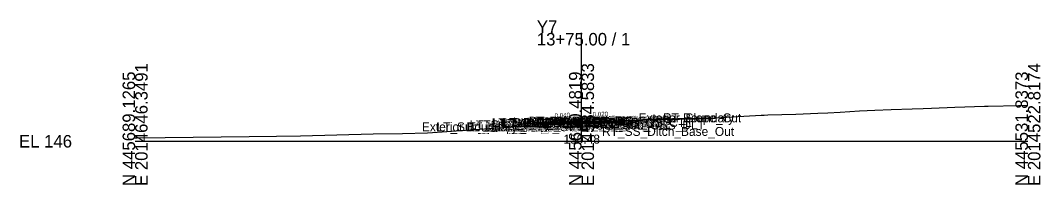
# Model space of a CAD drawing. Extents: x -26 to 203, y -10 to 7527.
# Drawn here: x -25.7 to 202.8, y 7490.3 to 7527 of the extents above; entities that cross this region are included whole.
import ezdxf

# ---------------------------------------------------------------- set-up
doc = ezdxf.new("R2010")
doc.units = 0
for name, color, linetype in [('Exist CMT Pavement', 7, 'Continuous'), ('Exist Cross Section Cell', 7, 'Continuous'), ('Exist XS Center Line Elevation Label', 7, 'Continuous'), ('Exist XS Ground Line', 7, 'Continuous'), ('Prop CMT Pvmt Course 1', 7, 'Continuous'), ('Prop CMT Pvmt Course 1 Wedge', 7, 'Continuous'), ('Prop CMT Pvmt Course 2', 7, 'Continuous'), ('Prop CMT Pvmt Course 2 Wedge', 7, 'Continuous'), ('Prop CMT Pvmt Course 3', 7, 'Continuous'), ('Prop CMT Pvmt Course 3 Wedge', 7, 'Continuous'), ('Prop CMT Pvmt Surface', 7, 'Continuous'), ('Prop CMT Pvmt Surface Shoulder', 7, 'Continuous'), ('Prop CMT Pvmt Wedge Surface 1', 7, 'Continuous'), ('Prop CMT Pvmt Wedge Surface 2', 7, 'Continuous'), ('Prop CMT Pvmt Wedge Surface 3', 7, 'Continuous'), ('Prop CMT Shld Paved Course 1', 7, 'Continuous'), ('Prop CMT Shld Paved Course 2', 7, 'Continuous'), ('Prop CMT Shld Paved Course 3', 7, 'Continuous'), ('Prop CMT Slope Grass', 7, 'Continuous'), ('Prop CMT Subgrade Earthwork', 7, 'Continuous'), ('Prop XS Earthwork Shape', 7, 'Continuous'), ('Prop XS SE Text', 7, 'Continuous'), ('Prop XS Side Slope Text', 7, 'Continuous'), ('Scratch_Level_0', 7, 'Continuous')]:
    doc.layers.add(name, color=color, linetype=linetype)

msp = doc.modelspace()

# ---------------------------------------------------------------- linework, layer by layer
at = {"layer": 'Exist CMT Pavement'}
msp.add_lwpolyline([(92.55, 7504.17), (98.8, 7504.43), (99.58, 7504.47), (100, 7504.48), (101.24, 7504.49), (107.57, 7504.59)], dxfattribs=at)
at = {"layer": 'Exist Cross Section Cell'}
for p, q in [((100, 7500), (100, 7524.24)), ((0, 7500), (100, 7500)), ((100, 7500), (200, 7500))]:
    msp.add_line(p, q, dxfattribs=at)
at = {"layer": 'Exist XS Ground Line'}
msp.add_lwpolyline([(0, 7500.78), (0.48, 7500.79), (25.52, 7501.08), (31.67, 7501.15), (37.07, 7501.23), (53.32, 7501.64), (59.89, 7501.77), (65.51, 7501.87), (68.77, 7502.08), (84.52, 7503.23), (85.44, 7503.31), (90.98, 7503.89), (91.38, 7504.13), (91.72, 7504.13), (98.8, 7504.43), (99.58, 7504.47), (100, 7504.48), (101.24, 7504.49), (108.29, 7504.6), (108.58, 7504.86), (109, 7504.59), (113.67, 7504.72), (116.69, 7504.88), (117.85, 7504.9), (126.1, 7505.05), (127.54, 7505.12), (133.78, 7505.47), (140.26, 7505.83), (140.9, 7505.86), (141.72, 7505.89), (148.02, 7506.06), (152.97, 7506.29), (155.15, 7506.38), (157.91, 7506.52), (162.27, 7506.8), (165.69, 7506.95), (169.39, 7507.12), (174.1, 7507.24), (176.51, 7507.37), (178.41, 7507.41), (183.64, 7507.62), (190.29, 7507.87), (190.76, 7507.89), (191.13, 7507.89), (197.88, 7508.03), (200, 7508.08)], dxfattribs=at)
at = {"layer": 'Prop CMT Pvmt Course 1'}
for points in [[(100, 7504.5), (91.55, 7504.17)], [(91.55, 7504.17), (91.55, 7503.92)], [(91.55, 7503.92), (92.55, 7503.96)], [(92.55, 7504.08), (100, 7504.38)], [(92.55, 7503.96), (92.55, 7504.08)], [(100, 7504.5), (108.57, 7504.68)], [(107.57, 7504.53), (100, 7504.38)], [(100, 7504.25), (100, 7504.5)], [(100, 7504.25), (100, 7504.5)], [(100, 7504.38), (100, 7504.25), (100, 7504.25)], [(100, 7504.38), (100, 7504.25), (100, 7504.25)], [(107.57, 7504.41), (107.57, 7504.53)], [(108.57, 7504.43), (107.57, 7504.41)], [(108.57, 7504.68), (108.57, 7504.43)]]:
    msp.add_lwpolyline(points, dxfattribs=at)
at = {"layer": 'Prop CMT Pvmt Course 1 Wedge'}
for points in [[(100, 7504.38), (92.55, 7504.08)], [(100, 7504.38), (107.57, 7504.53)]]:
    msp.add_lwpolyline(points, dxfattribs=at)
at = {"layer": 'Prop CMT Pvmt Course 2'}
for points in [[(92.55, 7503.96), (91.55, 7503.92)], [(91.55, 7503.92), (91.55, 7503.67)], [(91.55, 7503.67), (92.55, 7503.71)], [(92.55, 7503.71), (92.55, 7503.96)], [(107.57, 7504.41), (108.57, 7504.43)], [(107.57, 7504.16), (107.57, 7504.41)], [(108.57, 7504.18), (107.57, 7504.16)], [(108.57, 7504.43), (108.57, 7504.18)]]:
    msp.add_lwpolyline(points, dxfattribs=at)
at = {"layer": 'Prop CMT Pvmt Course 2 Wedge'}
for points in [[(100, 7504.25), (92.55, 7503.96)], [(100, 7504.25), (107.57, 7504.41)]]:
    msp.add_lwpolyline(points, dxfattribs=at)
at = {"layer": 'Prop CMT Pvmt Course 3'}
for points in [[(92.55, 7503.71), (91.55, 7503.67)], [(91.55, 7503.67), (91.55, 7503.29)], [(91.55, 7503.29), (92.55, 7503.33)], [(92.55, 7503.33), (92.55, 7503.71)], [(107.57, 7504.16), (108.57, 7504.18)], [(107.57, 7503.78), (107.57, 7504.16)], [(108.57, 7503.8), (107.57, 7503.78)], [(108.57, 7504.18), (108.57, 7503.8)]]:
    msp.add_lwpolyline(points, dxfattribs=at)
at = {"layer": 'Prop CMT Pvmt Course 3 Wedge'}
for points in [[(100, 7504), (92.55, 7503.71)], [(100, 7504), (107.57, 7504.16)]]:
    msp.add_lwpolyline(points, dxfattribs=at)
at = {"layer": 'Prop CMT Pvmt Surface'}
for points in [[(100, 7504.5), (91.55, 7504.17)], [(100, 7504.5), (108.57, 7504.68)]]:
    msp.add_lwpolyline(points, dxfattribs=at)
at = {"layer": 'Prop CMT Pvmt Surface Shoulder'}
for points in [[(91.55, 7504.17), (91.55, 7504.17)], [(108.57, 7504.68), (108.57, 7504.68)]]:
    msp.add_lwpolyline(points, dxfattribs=at)
at = {"layer": 'Prop CMT Pvmt Wedge Surface 1'}
for points in [[(91.55, 7503.92), (91.55, 7504.17)], [(92.55, 7503.96), (91.55, 7503.92)], [(100, 7504.38), (92.55, 7504.08)], [(92.55, 7504.08), (92.55, 7503.96)], [(100, 7504.38), (107.57, 7504.53)], [(107.57, 7504.53), (107.57, 7504.41)], [(107.57, 7504.41), (108.57, 7504.43)], [(108.57, 7504.43), (108.57, 7504.68)]]:
    msp.add_lwpolyline(points, dxfattribs=at)
at = {"layer": 'Prop CMT Pvmt Wedge Surface 2'}
for points in [[(100, 7504.25), (91.55, 7503.92)], [(91.55, 7503.92), (91.55, 7504.17)], [(100, 7504.25), (108.57, 7504.43)], [(108.57, 7504.43), (108.57, 7504.68)]]:
    msp.add_lwpolyline(points, dxfattribs=at)
at = {"layer": 'Prop CMT Pvmt Wedge Surface 3'}
for points in [[(91.55, 7503.67), (91.55, 7504.17)], [(100, 7504), (91.55, 7503.67)], [(100, 7504), (108.57, 7504.18)], [(108.57, 7504.18), (108.57, 7504.68)]]:
    msp.add_lwpolyline(points, dxfattribs=at)
at = {"layer": 'Prop CMT Shld Paved Course 1'}
for points in [[(91.55, 7504.17), (91.3, 7503.91)], [(91.3, 7503.91), (91.55, 7503.92)], [(91.55, 7504.17), (91.55, 7504.17)], [(91.55, 7503.92), (91.55, 7504.17)], [(108.57, 7504.68), (108.57, 7504.68)], [(108.57, 7504.68), (108.82, 7504.42)], [(108.57, 7504.43), (108.57, 7504.68)], [(108.82, 7504.42), (108.57, 7504.43)]]:
    msp.add_lwpolyline(points, dxfattribs=at)
at = {"layer": 'Prop CMT Shld Paved Course 2'}
for points in [[(91.55, 7503.92), (91.3, 7503.91), (91.04, 7503.66)], [(91.04, 7503.66), (91.55, 7503.67)], [(91.55, 7503.67), (91.55, 7503.92)], [(108.57, 7504.43), (108.82, 7504.42), (109.08, 7504.17)], [(108.57, 7504.18), (108.57, 7504.43)], [(109.08, 7504.17), (108.57, 7504.18)]]:
    msp.add_lwpolyline(points, dxfattribs=at)
at = {"layer": 'Prop CMT Shld Paved Course 3'}
for points in [[(90.16, 7503.26), (91.55, 7503.29)], [(91.55, 7503.67), (91.04, 7503.66), (90.66, 7503.27)], [(91.55, 7503.29), (91.55, 7503.67)], [(108.57, 7503.8), (108.57, 7504.18)], [(108.57, 7504.18), (109.08, 7504.17), (109.46, 7503.78)], [(109.96, 7503.77), (108.57, 7503.8)]]:
    msp.add_lwpolyline(points, dxfattribs=at)
at = {"layer": 'Prop CMT Slope Grass'}
for points in [[(108.57, 7504.68), (128.53, 7505.18)], [(91.55, 7504.17), (85.55, 7503.69), (84.08, 7503.2)]]:
    msp.add_lwpolyline(points, dxfattribs=at)
at = {"layer": 'Prop CMT Subgrade Earthwork'}
msp.add_line((109.96, 7503.77), (113.69, 7504.8), dxfattribs=at)
for points in [[(90.16, 7503.26), (84.23, 7503.24)], [(91.55, 7503.29), (90.16, 7503.26)], [(92.55, 7503.33), (91.55, 7503.29)], [(92.55, 7503.33), (92.55, 7504.17)], [(107.57, 7503.78), (107.57, 7504.59)], [(107.57, 7503.78), (108.57, 7503.8)], [(108.57, 7503.8), (109.96, 7503.77)]]:
    msp.add_lwpolyline(points, dxfattribs=at)
at = {"layer": 'Prop XS Earthwork Shape'}
for points in [[(113.35, 7504.71), (113.67, 7504.72), (116.69, 7504.88), (126.1, 7505.05), (128.53, 7505.18), (113.69, 7504.8)], [(84.72, 7503.25), (84.23, 7503.24), (84.08, 7503.2), (84.52, 7503.23)], [(91.38, 7504.13), (91.72, 7504.13), (92.55, 7504.17), (92.55, 7503.33), (91.55, 7503.29), (90.16, 7503.26), (84.72, 7503.25), (85.44, 7503.31), (90.98, 7503.89)], [(108.29, 7504.6), (108.37, 7504.67), (108.57, 7504.68), (108.9, 7504.65), (109, 7504.59), (109.5, 7504.6), (113.35, 7504.71), (109.96, 7503.77), (108.57, 7503.8), (107.57, 7503.78), (107.57, 7504.59)], [(108.58, 7504.86), (108.9, 7504.65), (108.57, 7504.68), (108.37, 7504.67)]]:
    msp.add_lwpolyline(points, close=True, dxfattribs=at)

# ---------------------------------------------------------------- texts
at = {"layer": 'Exist Cross Section Cell'}
for s, p in [('Y7', (90, 7524.24)), ('13+75.00 / 1', (90, 7521.44)), ('EL 146', (-26, 7498.6))]:
    msp.add_text(s, height=2.8, dxfattribs=at).set_placement(p)
for s, p in [('E 2014646.3491', (2.8, 7490)), ('E 2014584.5833', (102.8, 7490)), ('E 2014522.8174', (202.8, 7490)), ('N 445689.1265', (0, 7490)), ('N 445610.4819', (100, 7490)), ('N 445531.8373', (200, 7490))]:
    msp.add_text(s, height=2.8, rotation=90, dxfattribs=at).set_placement(p)
at = {"layer": 'Exist XS Center Line Elevation Label'}
msp.add_text('150.48', height=2, dxfattribs=at).set_placement((95.96, 7499.48))
at = {"layer": 'Prop XS SE Text'}
for s, rotation, p in [('0.040', 2.2906, (93.99, 7505.26)), ('0.020', 1.1458, (102.51, 7505.55))]:
    msp.add_text(s, height=1, rotation=rotation, dxfattribs=at).set_placement(p)
at = {"layer": 'Prop XS Side Slope Text'}
msp.add_text('3:1', height=1, rotation=18.4332, dxfattribs=at).set_placement((83.86, 7503.91))
at = {"layer": 'Scratch_Level_0'}
for s, p in [('LT_Sub Tie Out', (79.89, 7503.16)), ('LT_PV_OEEOP_EG', (80.1, 7503.16)), ('LT_PV1_OEOT', (82.29, 7503.17)), ('LT_PS1_OEOP', (82.35, 7503.17)), ('LT_PV1_OEEOP', (82.43, 7503.08)), ('RT_PV_IEEOP_EG', (88.14, 7503.48)), ('LT_PV_IEEOP_EG', (88.19, 7503.48)), ('RT_PV2_IEEOP', (89.91, 7503.25)), ('RT_PV3_IEEOP', (89.91, 7503)), ('LT_PV2_IEEOP', (89.95, 7503.25)), ('LT_PV3_IEEOP', (89.95, 7503)), ('RT_PV1_IEEOP', (90.47, 7503.38)), ('LT_PV1_IEEOP', (90.52, 7503.38)), ('PV2_PGL', (93.91, 7503.25)), ('PV1_PGL', (94.47, 7503.5)), ('RT_Sub Tie Out', (94.86, 7503.59)), ('RT_PV_OEEOP_EG', (95.06, 7503.59)), ('RT_PS3_Shelf_Out', (95.51, 7503.16)), ('RT_PV2_OEEOP', (96.83, 7503.41)), ('RT_PV3_OEEOP', (96.83, 7503.16)), ('RT_PV1_OEEOP', (97.39, 7503.53)), ('RT_PV2_OEOT', (98.69, 7503.43)), ('RT_PV3_OEOT', (98.69, 7503.18)), ('RT_PS2_OEOP', (99.01, 7503.42)), ('RT_PV1_OEOT', (99.26, 7503.68)), ('RT_PS3_OEOP', (99.27, 7503.17)), ('RT_PS1_OEOP', (99.32, 7503.68)), ('RT_GS_OS_CTL', (103.89, 7503.2)), ('Exterior Boundary', (112.79, 7504.24)), ('RT_Slope_Cut', (118.24, 7504.24)), ('Exterior Boundary', (64.25, 7502.23)), ('LT_Sub_OSS_DLT', (67.51, 7502.23)), ('LT_Sub_Trench_Out', (74.36, 7502.26)), ('LT_Slope_Fill', (74.67, 7502.22)), ('LT_GS_OS_CTL', (74.92, 7502.69)), ('LT_PS3_Shelf_Out', (76.53, 7502.65)), ('LT_PS3_OEOP', (81.28, 7502.66)), ('LT_PS2_OEOP', (81.53, 7502.91)), ('LT_Sub_OEOT', (81.63, 7502.29)), ('LT_PV2_OEOT', (81.72, 7502.92)), ('LT_PV3_OEOT', (81.72, 7502.67)), ('LT_Sub_OEEOP', (81.76, 7502.33)), ('LT_PV2_OEEOP', (81.86, 7502.96)), ('LT_PV3_OEEOP', (81.86, 7502.71)), ('RT_Sub_Trench_Out', (94.12, 7502.77)), ('RT_Sub_OEEOP', (96.73, 7502.78)), ('RT_Sub_OEOT', (98.6, 7502.8)), ('RT_Sub_OSS_DLT', (104.16, 7502.64)), ('RT_SS_Ditch_Base_Out', (104.6, 7501.2))]:
    msp.add_text(s, height=2, dxfattribs=at).set_placement(p)

doc.saveas('drawing.dxf')
